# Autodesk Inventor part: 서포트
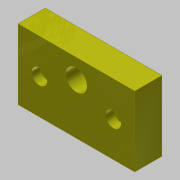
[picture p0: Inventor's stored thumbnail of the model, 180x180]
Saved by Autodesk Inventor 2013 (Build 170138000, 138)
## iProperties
Created: 2020-03
Part Number: 서포트
Material: 일반
Document SubType Name: Modeling
Designer: mduedu
Density: 2.71 g/cm^3
Mass: 71.7819 g
Surface Area: 79.3171 cm^2
Volume: 26.4878 cm^3
Author: mduedu
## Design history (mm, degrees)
sketch "스케치1"
  geometry: L1 (-30, 0)-(30, 0); L2 (30, 0)-(30, 36); L3 (30, 36)-(-30, 36); L4 (-30, 36)-(-30, 0); 2 further points
  constraints: 8 end point, 2 parallel, 1 coincident, 1 horizontal, 1 midpoint, 1 perpendicular
  dimensions: "d0" = 60 distance of L1.start L1.end; "d2" = 36 distance of L1.end L2.end
extrude "돌출1" new body sketch "스케치1" distance "d3" = 14; taper "d4" = 0 deg
sketch "스케치2"
  geometry: 3 further points
  constraints: 1 horizontal alignment
  dimensions: "d5" = 7 vertical distance of point (52, 7) point (30, 0); "d6" = 22 horizontal distance of point (8, 7) point (30, 0); "d7" = 44 distance of point (52, 7) point (8, 7)
hole "구멍1" sketch "스케치2" at (8, 7), (52, 7) diameter "d8" = 3.242; stored, may be unused: countersink angle "d12" = 90 deg, drill point angle "d14" = 118 deg; dims "d9" = 6, "d10" = 4, "d11" = 2, "d13" = 8
sketch "스케치3"
  geometry: L1 (30, 0)-(-30, 0) reference; 3 further points
  constraints: 1 midpoint, 1 vertical alignment
  dimensions: "d15" = 26 distance of point (0, 0) point (0, 26)
hole "구멍2" sketch "스케치3" at (0, 26) diameter "d16" = 11; stored, may be unused: countersink angle "d20" = 90 deg, drill point angle "d22" = 118 deg; dims "d17" = 8, "d18" = 15, "d19" = 3, "d21" = 10
sketch "스케치4"
  geometry: 3 further points
  constraints: 1 horizontal alignment
  dimensions: "d23" = 18 vertical distance of point (19, 18) point (0, 0); "d24" = 19 horizontal distance of point (-19, 18) point (0, 0); "d25" = 38 distance of point (19, 18) point (-19, 18)
hole "구멍3" sketch "스케치4" at (-19, 18), (19, 18) diameter "d26" = 4.5; stored, may be unused: countersink angle "d30" = 90 deg, drill point angle "d32" = 118 deg; dims "d27" = 8, "d28" = 8, "d29" = 4.4, "d31" = 10
sketch "스케치5"
  geometry: C1 r 2.25 at (-19, 18) reference; 1 further point
hole "구멍4" sketch "스케치5" at (-19, 18) diameter "d33" = 9; stored, may be unused: countersink angle "d37" = 90 deg, drill point angle "d39" = 0 deg; dims "d34" = 8, "d35" = 8, "d36" = 4.4, "d38" = 6
sketch "스케치6"
  geometry: C1 r 2.25 at (19, 18) reference; 1 further point
hole "구멍5" sketch "스케치6" at (19, 18) diameter "d40" = 9; stored, may be unused: countersink angle "d44" = 90 deg, drill point angle "d46" = 0 deg; dims "d41" = 8, "d42" = 8, "d43" = 4.4, "d45" = 6
node "솔리드1"
